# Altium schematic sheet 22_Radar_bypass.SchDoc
size 289 x 396 mm
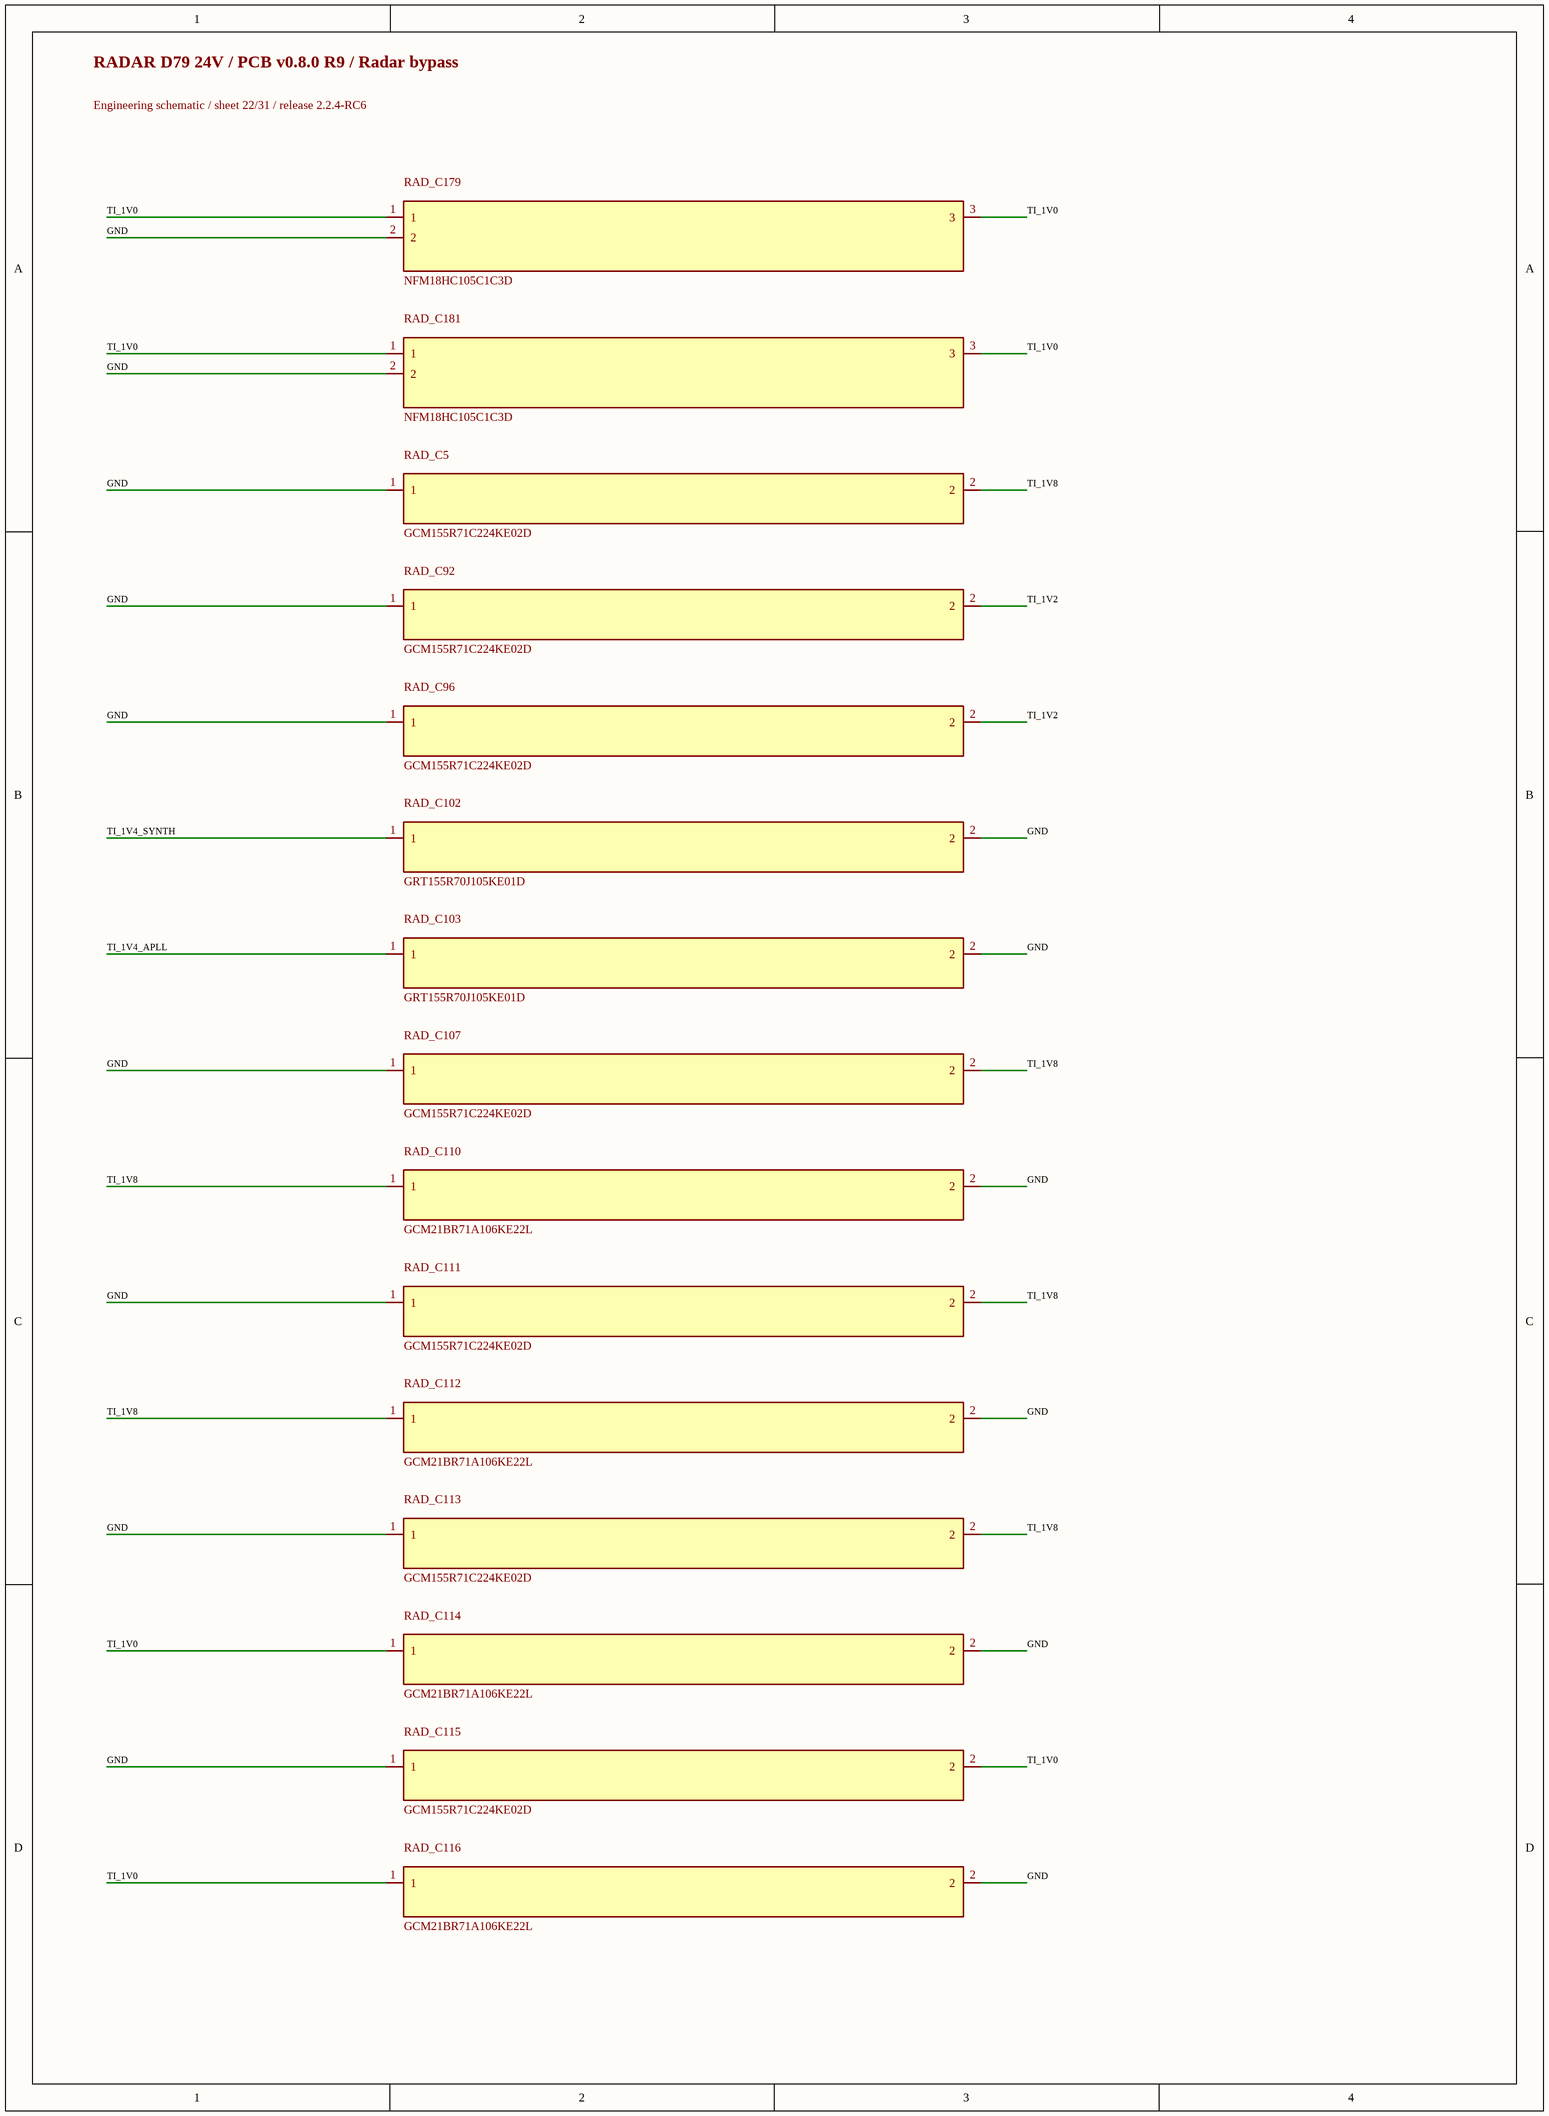
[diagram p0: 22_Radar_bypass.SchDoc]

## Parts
RAD_C5  GCM155R71C224KE02D  [0402L]
RAD_C92  GCM155R71C224KE02D  [0402L]
RAD_C96  GCM155R71C224KE02D  [0402L]
RAD_C102  GRT155R70J105KE01D  [FP-GRT155R70J105KE01D_0402-MFG]
RAD_C103  GRT155R70J105KE01D  [FP-GRT155R70J105KE01D_0402-MFG]
RAD_C107  GCM155R71C224KE02D  [0402L]
RAD_C110  GCM21BR71A106KE22L  [0805L]
RAD_C111  GCM155R71C224KE02D  [0402L]
RAD_C112  GCM21BR71A106KE22L  [0805L]
RAD_C113  GCM155R71C224KE02D  [0402L]
RAD_C114  GCM21BR71A106KE22L  [0805L]
RAD_C115  GCM155R71C224KE02D  [0402L]
RAD_C116  GCM21BR71A106KE22L  [0805L]
RAD_C179  NFM18HC105C1C3D  [FP-NFM18HC105C1C3D_0603-MFG]
RAD_C181  NFM18HC105C1C3D  [FP-NFM18HC105C1C3D_0603-MFG]

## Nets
GND: RAD_C5.1 RAD_C92.1 RAD_C96.1 RAD_C102.2 RAD_C103.2 RAD_C107.1 RAD_C110.2 RAD_C111.1 RAD_C112.2 RAD_C113.1 RAD_C114.2 RAD_C115.1 RAD_C116.2 RAD_C179.2 RAD_C181.2
TI_1V0: RAD_C114.1 RAD_C115.2 RAD_C116.1 RAD_C179.1 RAD_C179.3 RAD_C181.1 RAD_C181.3
TI_1V2: RAD_C92.2 RAD_C96.2
TI_1V4_APLL: RAD_C103.1
TI_1V4_SYNTH: RAD_C102.1
TI_1V8: RAD_C5.2 RAD_C107.2 RAD_C110.1 RAD_C111.2 RAD_C112.1 RAD_C113.2

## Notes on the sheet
- RADAR D79 24V / PCB v0.8.0 R9 / Radar bypass
- Engineering schematic / sheet 22/31 / release 2.2.4-RC6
